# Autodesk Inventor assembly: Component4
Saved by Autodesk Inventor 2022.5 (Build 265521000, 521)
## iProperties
Created: 2024-12
Part Number: Component4
Document SubType Name: Assembly
Designer: AdminForWorker
Title: Component4
Author: AdminForWorker
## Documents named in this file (2)
- c:\worker\convert-fusion-r05-cosv3\tmp\job-1\35\temp\files\545dca92-a972-481a-9197-dd1a1176500e\Component4_1.iam
- c:\worker\convert-fusion-r05-cosv3\tmp\job-1\35\temp\files\545dca92-a972-481a-9197-dd1a1176500e\Component5.ipt
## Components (1 placed, 1 different names)
1. Component5:1
